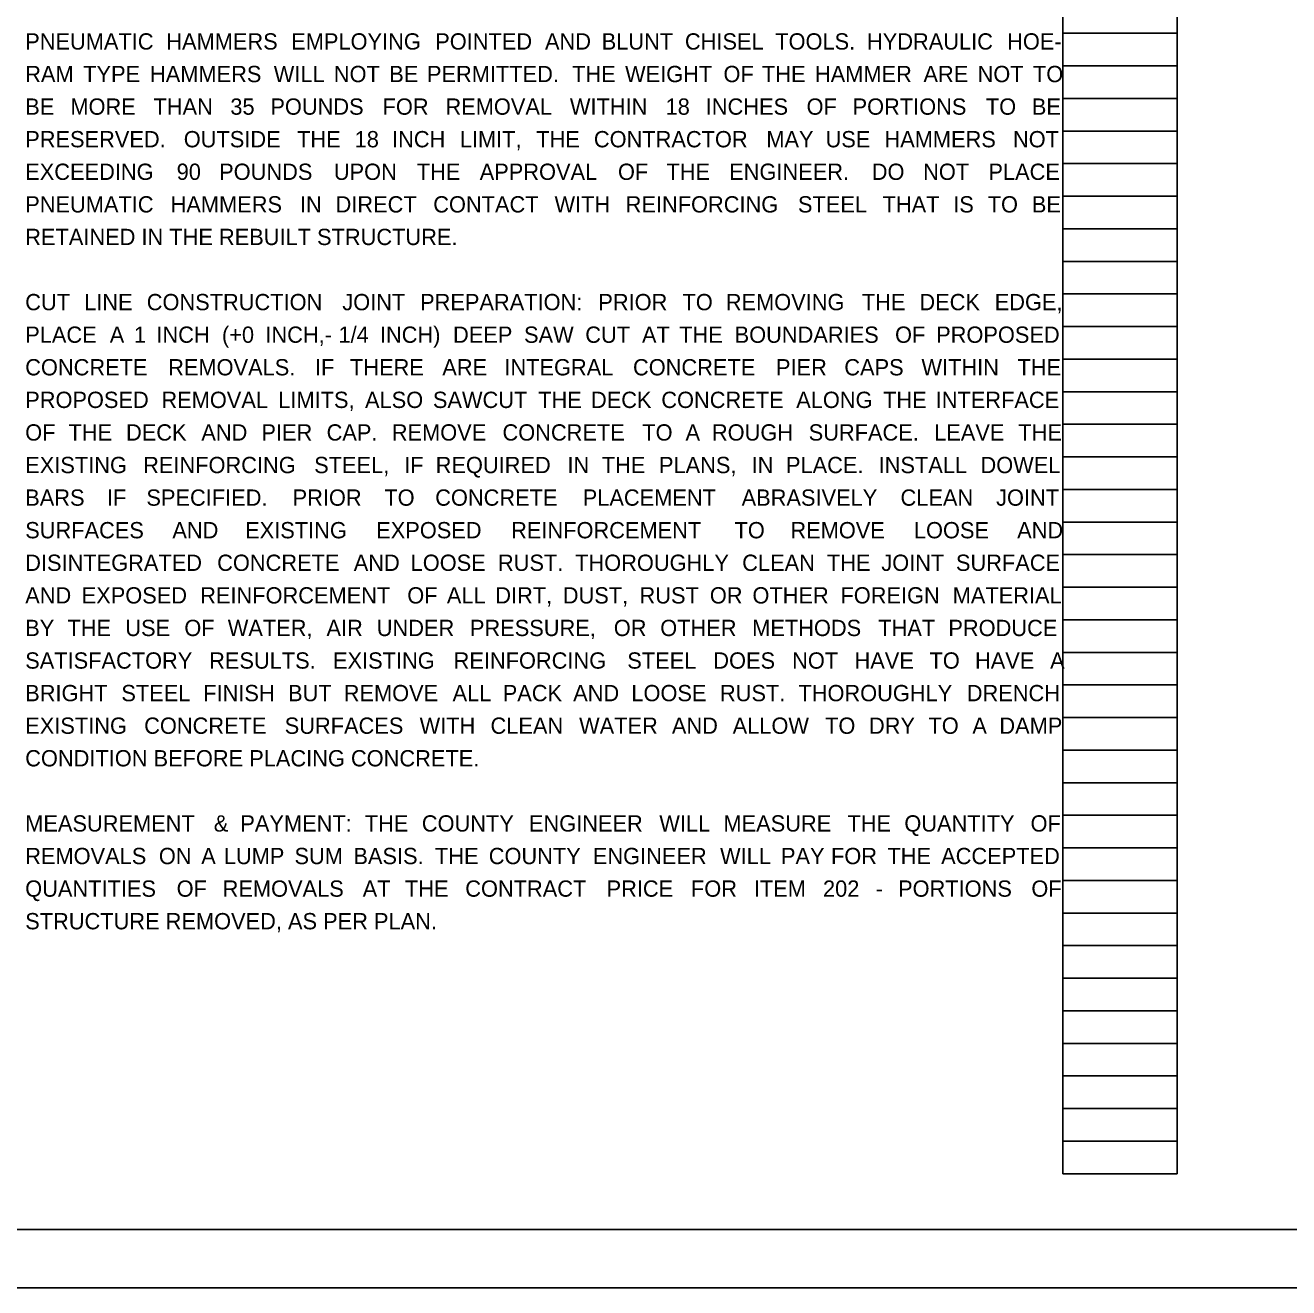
# Model space of a CAD drawing. Extents: x 0 to 64.5, y 0 to 22.
# Drawn here: x 12.29 to 23.15, y 0 to 10.85 of the extents above; entities that cross this region are included whole.
import ezdxf

# ---------------------------------------------------------------- set-up
doc = ezdxf.new("R2010")
doc.units = 0
for name, color, linetype in [('SC_Scratch1', 7, 'Continuous'), ('SH_Border', 7, 'Continuous'), ('SH_Cut_Line', 7, 'Continuous'), ('SH_Text', 7, 'Continuous')]:
    doc.layers.add(name, color=color, linetype=linetype)

msp = doc.modelspace()

# ---------------------------------------------------------------- linework, layer by layer
at = {"layer": 'SC_Scratch1'}
for p, q in [((21.207, 0.98), (21.207, 21.14)), ((22.187, 0.98), (22.187, 21.14)), ((21.207, 10.78), (22.187, 10.78)), ((21.207, 10.5), (22.187, 10.5)), ((21.207, 10.22), (22.187, 10.22)), ((21.207, 9.94), (22.187, 9.94)), ((21.207, 9.66), (22.187, 9.66)), ((21.207, 9.38), (22.187, 9.38)), ((21.207, 9.1), (22.187, 9.1)), ((21.207, 8.82), (22.187, 8.82)), ((21.207, 8.54), (22.187, 8.54)), ((21.207, 8.26), (22.187, 8.26)), ((21.207, 7.98), (22.187, 7.98)), ((21.207, 7.7), (22.187, 7.7)), ((21.207, 7.42), (22.187, 7.42)), ((21.207, 7.14), (22.187, 7.14)), ((21.207, 6.86), (22.187, 6.86)), ((21.207, 6.58), (22.187, 6.58)), ((21.207, 6.3), (22.187, 6.3)), ((21.207, 6.02), (22.187, 6.02)), ((21.207, 5.74), (22.187, 5.74)), ((21.207, 5.46), (22.187, 5.46)), ((21.207, 5.18), (22.187, 5.18)), ((21.207, 4.9), (22.187, 4.9)), ((21.207, 4.62), (22.187, 4.62)), ((21.207, 4.34), (22.187, 4.34)), ((21.207, 4.06), (22.187, 4.06)), ((21.207, 3.78), (22.187, 3.78)), ((21.207, 3.5), (22.187, 3.5)), ((21.207, 3.22), (22.187, 3.22)), ((21.207, 2.94), (22.187, 2.94)), ((21.207, 2.66), (22.187, 2.66)), ((21.207, 2.38), (22.187, 2.38)), ((21.207, 2.1), (22.187, 2.1)), ((21.207, 1.82), (22.187, 1.82)), ((21.207, 1.54), (22.187, 1.54)), ((21.207, 1.26), (22.187, 1.26)), ((21.207, 0.98), (22.187, 0.98))]:
    msp.add_line(p, q, dxfattribs=at)
msp.add_lwpolyline([(0, 22), (34, 22), (34, 0), (0, 0)], close=True, dxfattribs=at)
at = {"layer": 'SH_Border'}
msp.add_lwpolyline([(1.5, 21.5), (33.5, 21.5), (33.5, 0.5), (1.5, 0.5)], close=True, dxfattribs=at)
at = {"layer": 'SH_Cut_Line'}
msp.add_lwpolyline([(0, 0), (34, 0), (34, 22), (0, 22)], close=True, dxfattribs=at)

# ---------------------------------------------------------------- texts
at = {"layer": 'SH_Text'}
for s, p in [('PNEUMATIC ', (12.293, 10.64)), ('HAMMERS ', (13.505, 10.64)), ('EMPLOYING ', (14.578, 10.64)), ('POINTED ', (15.815, 10.64)), ('AND ', (16.758, 10.64)), ('BLUNT ', (17.245, 10.64)), ('CHISEL ', (17.96, 10.64)), ('TOOLS. ', (18.736, 10.64)), ('HYDRAULIC ', (19.524, 10.64)), ('HOE-', (20.728, 10.64)), ('RAM ', (12.293, 10.36)), ('TYPE ', (12.791, 10.36)), ('HAMMERS ', (13.365, 10.36)), ('WILL ', (14.428, 10.36)), ('NOT ', (14.944, 10.36)), ('BE ', (15.42, 10.36)), ('PERMITTED. ', (15.744, 10.36)), ('THE ', (16.991, 10.36)), ('WEIGHT ', (17.446, 10.36)), ('OF ', (18.291, 10.36)), ('THE ', (18.622, 10.36)), ('HAMMER ', (19.077, 10.36)), ('ARE ', (20.009, 10.36)), ('NOT ', (20.474, 10.36)), ('TO ', (20.95, 10.36)), ('BE ', (12.293, 10.08)), ('MORE ', (12.681, 10.08)), ('THAN ', (13.395, 10.08)), ('35 ', (14.055, 10.08)), ('POUNDS ', (14.399, 10.08)), ('FOR ', (15.363, 10.08)), ('REMOVAL ', (15.903, 10.08)), ('WITHIN ', (16.972, 10.08)), ('18 ', (17.794, 10.08)), ('INCHES ', (18.139, 10.08)), ('OF ', (19.005, 10.08)), ('PORTIONS ', (19.4, 10.08)), ('TO ', (20.545, 10.08)), ('BE ', (20.94, 10.08)), ('PRESERVED. ', (12.293, 9.8)), ('OUTSIDE ', (13.655, 9.8)), ('THE ', (14.628, 9.8)), ('18 ', (15.123, 9.8)), ('INCH ', (15.444, 9.8)), ('LIMIT, ', (16.026, 9.8)), ('THE ', (16.683, 9.8)), ('CONTRACTOR ', (17.178, 9.8)), ('MAY ', (18.659, 9.8)), ('USE ', (19.168, 9.8)), ('HAMMERS ', (19.674, 9.8)), ('NOT ', (20.778, 9.8)), ('EXCEEDING ', (12.293, 9.52)), ('90 ', (13.594, 9.52)), ('POUNDS ', (13.959, 9.52)), ('UPON ', (14.944, 9.52)), ('THE ', (15.657, 9.52)), ('APPROVAL ', (16.197, 9.52)), ('OF ', (17.385, 9.52)), ('THE ', (17.801, 9.52)), ('ENGINEER. ', (18.34, 9.52)), ('DO ', (19.565, 9.52)), ('NOT ', (20.006, 9.52)), ('PLACE ', (20.567, 9.52)), ('PNEUMATIC ', (12.293, 9.24)), ('HAMMERS ', (13.542, 9.24)), ('IN ', (14.653, 9.24)), ('DIRECT ', (14.959, 9.24)), ('CONTACT ', (15.798, 9.24)), ('WITH ', (16.84, 9.24)), ('REINFORCING ', (17.451, 9.24)), ('STEEL ', (18.931, 9.24)), ('THAT ', (19.658, 9.24)), ('IS ', (20.265, 9.24)), ('TO ', (20.561, 9.24)), ('BE ', (20.94, 9.24)), ('RETAINED IN THE REBUILT STRUCTURE.', (12.293, 8.96)), ('CUT ', (12.293, 8.4)), ('LINE ', (12.799, 8.4)), ('CONSTRUCTION ', (13.337, 8.4)), ('JOINT ', (15.017, 8.4)), ('PREPARATION: ', (15.685, 8.4)), ('PRIOR ', (17.216, 8.4)), ('TO ', (17.939, 8.4)), ('REMOVING ', (18.311, 8.4)), ('THE ', (19.48, 8.4)), ('DECK ', (19.974, 8.4)), ('EDGE, ', (20.621, 8.4)), ('PLACE ', (12.293, 8.12)), ('A ', (13.019, 8.12)), ('1 ', (13.227, 8.12)), ('INCH ', (13.42, 8.12)), ('(+0 ', (13.983, 8.12)), ('INCH,-', (14.356, 8.12)), ('1/4 ', (14.984, 8.12)), ('INCH) ', (15.34, 8.12)), ('DEEP ', (15.968, 8.12)), ('SAW ', (16.578, 8.12)), ('CUT ', (17.104, 8.12)), ('AT ', (17.591, 8.12)), ('THE ', (17.911, 8.12)), ('BOUNDARIES ', (18.387, 8.12)), ('OF ', (19.765, 8.12)), ('PROPOSED ', (20.118, 8.12)), ('CONCRETE ', (12.293, 7.84)), ('REMOVALS. ', (13.521, 7.84)), ('IF ', (14.782, 7.84)), ('THERE ', (15.083, 7.84)), ('ARE ', (15.876, 7.84)), ('INTEGRAL ', (16.409, 7.84)), ('CONCRETE ', (17.514, 7.84)), ('PIER ', (18.742, 7.84)), ('CAPS ', (19.329, 7.84)), ('WITHIN ', (19.992, 7.84)), ('THE ', (20.817, 7.84)), ('PROPOSED ', (12.293, 7.56)), ('REMOVAL ', (13.463, 7.56)), ('LIMITS, ', (14.467, 7.56)), ('ALSO ', (15.212, 7.56)), ('SAWCUT ', (15.795, 7.56)), ('THE ', (16.7, 7.56)), ('DECK ', (17.153, 7.56)), ('CONCRETE ', (17.757, 7.56)), ('ALONG ', (18.916, 7.56)), ('THE ', (19.662, 7.56)), ('INTERFACE ', (20.114, 7.56)), ('OF ', (12.293, 7.28)), ('THE ', (12.665, 7.28)), ('DECK ', (13.159, 7.28)), ('AND ', (13.806, 7.28)), ('PIER ', (14.322, 7.28)), ('CAP. ', (14.882, 7.28)), ('REMOVE ', (15.442, 7.28)), ('CONCRETE ', (16.393, 7.28)), ('TO ', (17.594, 7.28)), ('A ', (17.965, 7.28)), ('ROUGH ', (18.192, 7.28)), ('SURFACE. ', (19.023, 7.28)), ('LEAVE ', (20.101, 7.28)), ('THE ', (20.824, 7.28)), ('EXISTING ', (12.293, 7)), ('REINFORCING ', (13.306, 7)), ('STEEL, ', (14.775, 7)), ('IF ', (15.549, 7)), ('REQUIRED ', (15.819, 7)), ('IN ', (16.951, 7)), ('THE ', (17.246, 7)), ('PLANS, ', (17.737, 7)), ('IN ', (18.533, 7)), ('PLACE. ', (18.828, 7)), ('INSTALL ', (19.624, 7)), ('DOWEL ', (20.499, 7)), ('BARS ', (12.293, 6.72)), ('IF ', (12.995, 6.72)), ('SPECIFIED. ', (13.334, 6.72)), ('PRIOR ', (14.59, 6.72)), ('TO ', (15.378, 6.72)), ('CONCRETE ', (15.815, 6.72)), ('PLACEMENT ', (17.082, 6.72)), ('ABRASIVELY ', (18.447, 6.72)), ('CLEAN ', (19.812, 6.72)), ('JOINT ', (20.633, 6.72)), ('SURFACES ', (12.293, 6.44)), ('AND ', (13.557, 6.44)), ('EXISTING ', (14.182, 6.44)), ('EXPOSED ', (15.308, 6.44)), ('REINFORCEMENT ', (16.467, 6.44)), ('TO ', (18.386, 6.44)), ('REMOVE ', (18.866, 6.44)), ('LOOSE ', (19.927, 6.44)), ('AND ', (20.814, 6.44)), ('DISINTEGRATED ', (12.293, 6.16)), ('CONCRETE ', (13.942, 6.16)), ('AND ', (15.115, 6.16)), ('LOOSE ', (15.604, 6.16)), ('RUST. ', (16.354, 6.16)), ('THOROUGHLY ', (17.017, 6.16)), ('CLEAN ', (18.452, 6.16)), ('THE ', (19.18, 6.16)), ('JOINT ', (19.647, 6.16)), ('SURFACE ', (20.288, 6.16)), ('AND ', (12.293, 5.88)), ('EXPOSED ', (12.778, 5.88)), ('REINFORCEMENT ', (13.796, 5.88)), ('OF ', (15.575, 5.88)), ('ALL ', (15.915, 5.88)), ('DIRT, ', (16.331, 5.88)), ('DUST, ', (16.911, 5.88)), ('RUST ', (17.57, 5.88)), ('OR ', (18.174, 5.88)), ('OTHER ', (18.54, 5.88)), ('FOREIGN ', (19.296, 5.88)), ('MATERIAL ', (20.26, 5.88)), ('BY ', (12.293, 5.6)), ('THE ', (12.656, 5.6)), ('USE ', (13.153, 5.6)), ('OF ', (13.66, 5.6)), ('WATER, ', (14.033, 5.6)), ('AIR ', (14.881, 5.6)), ('UNDER ', (15.313, 5.6)), ('PRESSURE, ', (16.113, 5.6)), ('OR ', (17.349, 5.6)), ('OTHER ', (17.748, 5.6)), ('METHODS ', (18.538, 5.6)), ('THAT ', (19.621, 5.6)), ('PRODUCE ', (20.223, 5.6)), ('SATISFACTORY ', (12.293, 5.32)), ('RESULTS. ', (13.873, 5.32)), ('EXISTING ', (14.937, 5.32)), ('REINFORCING ', (15.973, 5.32)), ('STEEL ', (17.465, 5.32)), ('DOES ', (18.204, 5.32)), ('NOT ', (18.881, 5.32)), ('HAVE ', (19.417, 5.32)), ('TO ', (20.061, 5.32)), ('HAVE ', (20.452, 5.32)), ('A ', (21.097, 5.32)), ('BRIGHT ', (12.293, 5.04)), ('STEEL ', (13.119, 5.04)), ('FINISH ', (13.822, 5.04)), ('BUT ', (14.551, 5.04)), ('REMOVE ', (15.029, 5.04)), ('ALL ', (15.964, 5.04)), ('PACK ', (16.395, 5.04)), ('AND ', (17, 5.04)), ('LOOSE ', (17.5, 5.04)), ('RUST. ', (18.261, 5.04)), ('THOROUGHLY ', (18.935, 5.04)), ('DRENCH ', (20.381, 5.04)), ('EXISTING ', (12.293, 4.76)), ('CONCRETE ', (13.315, 4.76)), ('SURFACES ', (14.522, 4.76)), ('WITH ', (15.681, 4.76)), ('CLEAN ', (16.29, 4.76)), ('WATER ', (17.051, 4.76)), ('AND ', (17.848, 4.76)), ('ALLOW ', (18.37, 4.76)), ('TO ', (19.164, 4.76)), ('DRY ', (19.541, 4.76)), ('TO ', (20.052, 4.76)), ('A ', (20.429, 4.76)), ('DAMP ', (20.661, 4.76)), ('CONDITION BEFORE PLACING CONCRETE. ', (12.293, 4.48)), ('MEASUREMENT ', (12.293, 3.92)), ('& ', (13.913, 3.92)), ('PAYMENT: ', (14.141, 3.92)), ('THE ', (15.21, 3.92)), ('COUNTY ', (15.7, 3.92)), ('ENGINEER ', (16.62, 3.92)), ('WILL ', (17.74, 3.92)), ('MEASURE ', (18.291, 3.92)), ('THE ', (19.356, 3.92)), ('QUANTITY ', (19.845, 3.92)), ('OF ', (20.929, 3.92)), ('REMOVALS ', (12.293, 3.64)), ('ON ', (13.441, 3.64)), ('A ', (13.805, 3.64)), ('LUMP ', (13.999, 3.64)), ('SUM ', (14.606, 3.64)), ('BASIS. ', (15.112, 3.64)), ('THE ', (15.813, 3.64)), ('COUNTY ', (16.275, 3.64)), ('ENGINEER ', (17.169, 3.64)), ('WILL ', (18.262, 3.64)), ('PAY ', (18.785, 3.64)), ('FOR ', (19.215, 3.64)), ('THE ', (19.699, 3.64)), ('ACCEPTED ', (20.161, 3.64)), ('QUANTITIES ', (12.293, 3.36)), ('OF ', (13.594, 3.36)), ('REMOVALS ', (13.989, 3.36)), ('AT ', (15.192, 3.36)), ('THE ', (15.555, 3.36)), ('CONTRACT ', (16.073, 3.36)), ('PRICE ', (17.287, 3.36)), ('FOR ', (18.012, 3.36)), ('ITEM ', (18.552, 3.36)), ('202 ', (19.146, 3.36)), ('PORTIONS ', (19.791, 3.36)), ('OF ', (20.936, 3.36)), ('- ', (19.599, 3.36)), ('STRUCTURE REMOVED, AS PER PLAN.  ', (12.293, 3.08))]:
    msp.add_text(s, height=0.14, dxfattribs=at).set_placement(p)

doc.saveas('drawing.dxf')
